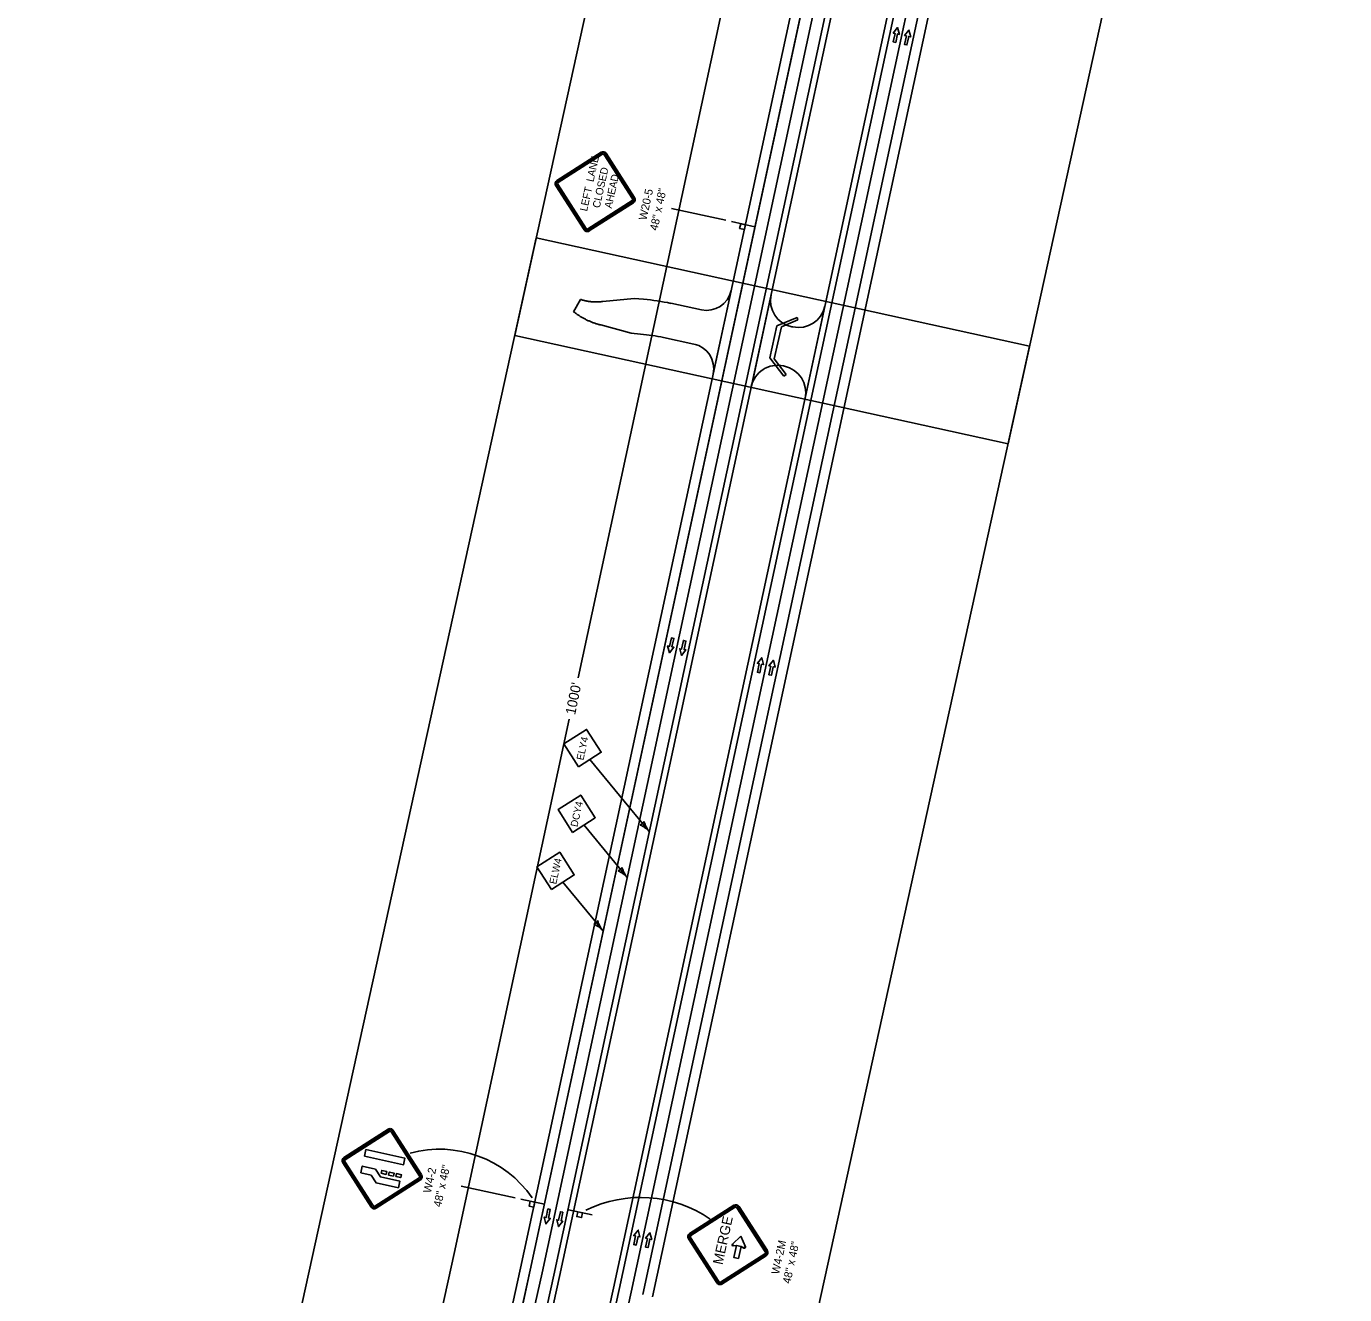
# Model space of a CAD drawing. Extents: x 14104283 to 14121738, y 8635219 to 8671666.
# Drawn here: x 14108108 to 14109426, y 8643186 to 8644454 of the extents above; entities that cross this region are included whole.
import ezdxf

# ---------------------------------------------------------------- set-up
doc = ezdxf.new("R2010")
doc.units = 0
for name, color, linetype in [('Cell', 7, 'Continuous'), ('Default', 7, 'Continuous'), ('dsnNonPlotable', 7, 'Continuous'), ('dsnPaintExistingBrokenLaneLineWhite', 7, 'Continuous'), ('dsnPaintExistingEdgeLineLeftYellow', 7, 'Continuous'), ('dsnPaintExistingEdgeLineRightWhite', 7, 'Continuous'), ('dsnStdLabel', 7, 'Continuous'), ('dsnStgShadingPrevPav', 7, 'Continuous')]:
    doc.layers.add(name, color=color, linetype=linetype)

msp = doc.modelspace()

# ---------------------------------------------------------------- linework, layer by layer
at = {"layer": 'Cell'}
for p, q in [((14108682.3, 8644328.2), (14108638.1, 8644299.9)), ((14108682.8, 8644327.4), (14108683.7, 8644326.1)), ((14108685.4, 8644325.7), (14108686.7, 8644326.6)), ((14108715.8, 8644282.8), (14108687.5, 8644327.1)), ((14108639.5, 8644297.8), (14108638.6, 8644299.1)), ((14108637, 8644294.7), (14108665.3, 8644250.5)), ((14108637.8, 8644295.2), (14108639.1, 8644296.1)), ((14108670.4, 8644249.4), (14108714.7, 8644277.7)), ((14108713.3, 8644279.8), (14108714.2, 8644278.4)), ((14108715, 8644282.3), (14108713.7, 8644281.5)), ((14108812.7, 8644258.8), (14108836.2, 8644253.7)), ((14108667.4, 8644251.8), (14108666.1, 8644251)), ((14108669.9, 8644250.2), (14108669.1, 8644251.5)), ((14108425.2, 8643322.8), (14108469.5, 8643351.1)), ((14108469.5, 8643351.1), (14108425.2, 8643322.8)), ((14108425.7, 8643322), (14108470, 8643350.3)), ((14108470.8, 8643349), (14108426.6, 8643320.7)), ((14108500.8, 8643304.4), (14108472.5, 8643348.6)), ((14108473.9, 8643349.5), (14108502.1, 8643305.2)), ((14108474.6, 8643350), (14108502.9, 8643305.8)), ((14108502.9, 8643305.8), (14108474.6, 8643350)), ((14108452.4, 8643273.4), (14108424.1, 8643317.6)), ((14108424.1, 8643317.6), (14108452.4, 8643273.4)), ((14108424.1, 8643317.6), (14108424.1, 8643317.6)), ((14108453.2, 8643273.9), (14108424.9, 8643318.1)), ((14108426.2, 8643319), (14108426.2, 8643319)), ((14108426.2, 8643319), (14108454.5, 8643274.8)), ((14108456.2, 8643274.4), (14108500.5, 8643302.7)), ((14108501.3, 8643301.4), (14108457.1, 8643273.1)), ((14108501.8, 8643300.6), (14108457.6, 8643272.3)), ((14108457.6, 8643272.3), (14108501.8, 8643300.6)), ((14108602.2, 8643281.2), (14108625.7, 8643276.1)), ((14108649.9, 8643270.7), (14108673.3, 8643265.6)), ((14108815.1, 8643275.2), (14108770.9, 8643246.9)), ((14108815.6, 8643274.4), (14108816.5, 8643273.1)), ((14108818.2, 8643272.7), (14108819.5, 8643273.5)), ((14108848.6, 8643229.8), (14108820.3, 8643274)), ((14108770.5, 8643242.2), (14108771.9, 8643243)), ((14108772.2, 8643244.8), (14108771.4, 8643246.1)), ((14108769.7, 8643241.7), (14108798, 8643197.5)), ((14108814.4, 8643235.6), (14108813.7, 8643236.4)), ((14108814.5, 8643234.6), (14108814.4, 8643235.6)), ((14108825.7, 8643233.2), (14108825.2, 8643232.3)), ((14108826.7, 8643233.5), (14108825.7, 8643233.2)), ((14108847.8, 8643229.3), (14108846.5, 8643228.5)), ((14108803.2, 8643196.3), (14108847.4, 8643224.6)), ((14108846.1, 8643226.7), (14108846.9, 8643225.4)), ((14108800.1, 8643198.8), (14108798.8, 8643198)), ((14108802.7, 8643197.1), (14108801.9, 8643198.4))]:
    msp.add_line(p, q, dxfattribs=at)
for points in [[(14108976.9, 8644437.9), (14108974.4, 8644438.4), (14108976.3, 8644446.9), (14108974.5, 8644447.3), (14108978.8, 8644452.8), (14108980.6, 8644446), (14108978.7, 8644446.4)], [(14108988.2, 8644435.4), (14108985.7, 8644435.9), (14108987.6, 8644444.5), (14108985.8, 8644444.9), (14108990.1, 8644450.3), (14108991.9, 8644443.5), (14108990, 8644443.9)], [(14108682.8, 8644327.4), (14108638.6, 8644299.1), (14108639.5, 8644297.8), (14108683.7, 8644326.1), (14108682.8, 8644327.4)], [(14108715, 8644282.3), (14108686.7, 8644326.6), (14108685.4, 8644325.7), (14108713.7, 8644281.5), (14108715, 8644282.3)], [(14108637.8, 8644295.2), (14108666.1, 8644251), (14108667.4, 8644251.8), (14108639.1, 8644296.1), (14108637.8, 8644295.2)], [(14108669.9, 8644250.2), (14108714.2, 8644278.4), (14108713.3, 8644279.8), (14108669.1, 8644251.5), (14108669.9, 8644250.2)], [(14108826.7, 8644255.7), (14108822, 8644256.7), (14108820.9, 8644251.9), (14108825.7, 8644250.9)], [(14108752.6, 8643842.5), (14108755.1, 8643842), (14108753.2, 8643833.5), (14108755.1, 8643833.1), (14108750.7, 8643827.6), (14108748.9, 8643834.4), (14108750.8, 8643834)], [(14108764.7, 8643839.9), (14108767.2, 8643839.3), (14108765.3, 8643830.8), (14108767.1, 8643830.4), (14108762.7, 8643825), (14108761, 8643831.7), (14108762.8, 8643831.3)], [(14108841.1, 8643807.7), (14108838.6, 8643808.2), (14108840.5, 8643816.8), (14108838.7, 8643817.2), (14108843, 8643822.6), (14108844.8, 8643815.8), (14108842.9, 8643816.2)], [(14108852.6, 8643805.1), (14108850.2, 8643805.7), (14108852, 8643814.2), (14108850.2, 8643814.6), (14108854.6, 8643820.1), (14108856.3, 8643813.3), (14108854.5, 8643813.7)], [(14108445.8, 8643324.2), (14108484.9, 8643315.6), (14108486.3, 8643322.2), (14108447.2, 8643330.8)], [(14108452.5, 8643305.4), (14108457.5, 8643297.5), (14108479.8, 8643292.6), (14108481.3, 8643299.2), (14108461.7, 8643303.5), (14108456.7, 8643311.4), (14108443.6, 8643314.3), (14108442.2, 8643307.7)], [(14108462.5, 8643307.1), (14108463.1, 8643310), (14108468, 8643308.9), (14108467.4, 8643306)], [(14108469.8, 8643305.4), (14108470.5, 8643308.4), (14108475.4, 8643307.3), (14108474.7, 8643304.4)], [(14108477.2, 8643303.8), (14108477.8, 8643306.8), (14108482.7, 8643305.7), (14108482, 8643302.8)], [(14108616.2, 8643278.1), (14108611.4, 8643279.1), (14108610.4, 8643274.3), (14108615.2, 8643273.3)], [(14108629.2, 8643271.5), (14108631.6, 8643270.9), (14108629.8, 8643262.4), (14108631.6, 8643262), (14108627.2, 8643256.5), (14108625.5, 8643263.3), (14108627.3, 8643262.9)], [(14108815.6, 8643274.4), (14108771.4, 8643246.1), (14108772.2, 8643244.8), (14108816.5, 8643273.1), (14108815.6, 8643274.4)], [(14108847.8, 8643229.3), (14108819.5, 8643273.5), (14108818.2, 8643272.7), (14108846.5, 8643228.5), (14108847.8, 8643229.3)], [(14108641.7, 8643268.7), (14108644.1, 8643268.2), (14108642.3, 8643259.6), (14108644.1, 8643259.2), (14108639.7, 8643253.8), (14108638, 8643260.6), (14108639.8, 8643260.2)], [(14108663.9, 8643267.6), (14108659.1, 8643268.6), (14108658.1, 8643263.8), (14108662.9, 8643262.8)], [(14108717.5, 8643235.4), (14108715.1, 8643235.9), (14108716.9, 8643244.5), (14108715.1, 8643244.9), (14108719.5, 8643250.3), (14108721.2, 8643243.5), (14108719.4, 8643243.9)], [(14108729.3, 8643232.8), (14108726.8, 8643233.3), (14108728.7, 8643241.9), (14108726.9, 8643242.3), (14108731.2, 8643247.7), (14108733, 8643240.9), (14108731.1, 8643241.3)], [(14108770.5, 8643242.2), (14108798.8, 8643198), (14108800.1, 8643198.8), (14108771.9, 8643243), (14108770.5, 8643242.2)], [(14108822.2, 8643244.3), (14108813.7, 8643236.4), (14108814.4, 8643235.6), (14108814.5, 8643234.6), (14108817.6, 8643235), (14108822.5, 8643233.9), (14108825.2, 8643232.3), (14108825.7, 8643233.2), (14108826.7, 8643233.5), (14108822.2, 8643244.3)], [(14108819.9, 8643222), (14108815, 8643223), (14108817.6, 8643235), (14108822.5, 8643233.9), (14108819.9, 8643222)], [(14108802.7, 8643197.1), (14108846.9, 8643225.4), (14108846.1, 8643226.7), (14108801.9, 8643198.4), (14108802.7, 8643197.1)]]:
    msp.add_lwpolyline(points, close=True, dxfattribs=at)
for points in [[(14108978.7, 8644446.4), (14108980.6, 8644446), (14108978.8, 8644452.8), (14108974.5, 8644447.3), (14108976.3, 8644446.9), (14108974.4, 8644438.4), (14108976.9, 8644437.9), (14108978.7, 8644446.4)], [(14108990, 8644443.9), (14108991.9, 8644443.5), (14108990.1, 8644450.3), (14108985.8, 8644444.9), (14108987.6, 8644444.5), (14108985.7, 8644435.9), (14108988.2, 8644435.4), (14108990, 8644443.9)], [(14108826.7, 8644255.7), (14108822, 8644256.7), (14108820.9, 8644251.9), (14108825.7, 8644250.9), (14108826.7, 8644255.7)], [(14108750.8, 8643834), (14108748.9, 8643834.4), (14108750.7, 8643827.6), (14108755.1, 8643833.1), (14108753.2, 8643833.5), (14108755.1, 8643842), (14108752.6, 8643842.5), (14108750.8, 8643834)], [(14108762.8, 8643831.3), (14108761, 8643831.7), (14108762.7, 8643825), (14108767.1, 8643830.4), (14108765.3, 8643830.8), (14108767.2, 8643839.3), (14108764.7, 8643839.9), (14108762.8, 8643831.3)], [(14108842.9, 8643816.2), (14108844.8, 8643815.8), (14108843, 8643822.6), (14108838.7, 8643817.2), (14108840.5, 8643816.8), (14108838.6, 8643808.2), (14108841.1, 8643807.7), (14108842.9, 8643816.2)], [(14108854.5, 8643813.7), (14108856.3, 8643813.3), (14108854.6, 8643820.1), (14108850.2, 8643814.6), (14108852, 8643814.2), (14108850.2, 8643805.7), (14108852.6, 8643805.1), (14108854.5, 8643813.7)], [(14108470, 8643350.3), (14108425.7, 8643322)], [(14108470.8, 8643349), (14108426.6, 8643320.7)], [(14108500.8, 8643304.4), (14108472.5, 8643348.6)], [(14108502.1, 8643305.2), (14108473.9, 8643349.5)], [(14108424.9, 8643318.1), (14108453.2, 8643273.9)], [(14108426.2, 8643319), (14108454.5, 8643274.8)], [(14108456.2, 8643274.4), (14108500.5, 8643302.7)], [(14108457.1, 8643273.1), (14108501.3, 8643301.4)], [(14108616.2, 8643278.1), (14108611.4, 8643279.1), (14108610.4, 8643274.3), (14108615.2, 8643273.3), (14108616.2, 8643278.1)], [(14108627.3, 8643262.9), (14108625.5, 8643263.3), (14108627.2, 8643256.5), (14108631.6, 8643262), (14108629.8, 8643262.4), (14108631.6, 8643270.9), (14108629.2, 8643271.5), (14108627.3, 8643262.9)], [(14108639.8, 8643260.2), (14108638, 8643260.6), (14108639.7, 8643253.8), (14108644.1, 8643259.2), (14108642.3, 8643259.6), (14108644.1, 8643268.2), (14108641.7, 8643268.7), (14108639.8, 8643260.2)], [(14108663.9, 8643267.6), (14108659.1, 8643268.6), (14108658.1, 8643263.8), (14108662.9, 8643262.8), (14108663.9, 8643267.6)], [(14108719.4, 8643243.9), (14108721.2, 8643243.5), (14108719.5, 8643250.3), (14108715.1, 8643244.9), (14108716.9, 8643244.5), (14108715.1, 8643235.9), (14108717.5, 8643235.4), (14108719.4, 8643243.9)], [(14108731.1, 8643241.3), (14108733, 8643240.9), (14108731.2, 8643247.7), (14108726.9, 8643242.3), (14108728.7, 8643241.9), (14108726.8, 8643233.3), (14108729.3, 8643232.8), (14108731.1, 8643241.3)]]:
    msp.add_lwpolyline(points, dxfattribs=at)
for centre, radius, start, end in [((14108684.4, 8644325), 3.75, 32.608, 122.6076), ((14108684.4, 8644325), 2.81, 32.608, 122.6076), ((14108684.4, 8644325), 1.25, 32.608, 122.6076), ((14108640.1, 8644296.7), 3.75, 122.6078, 212.6076), ((14108640.1, 8644296.7), 2.81, 122.6078, 212.6076), ((14108640.1, 8644296.7), 1.25, 122.6078, 212.6076), ((14108712.7, 8644280.8), 1.25, 302.6078, 32.608), ((14108712.7, 8644280.8), 2.81, 302.6078, 32.608), ((14108712.7, 8644280.8), 3.75, 302.6078, 32.608), ((14108668.4, 8644252.5), 3.75, 212.6076, 302.6078), ((14108668.4, 8644252.5), 2.81, 212.6076, 302.6078), ((14108668.4, 8644252.5), 1.25, 212.6076, 302.6078), ((14108471.5, 8643348), 3.75, 32.6079, 122.6081), ((14108471.5, 8643348), 3.75, 32.6079, 122.6081), ((14108471.5, 8643348), 2.81, 32.6079, 122.6081), ((14108471.5, 8643348), 2.81, 32.6079, 122.6081), ((14108471.5, 8643348), 1.25, 32.6079, 122.6081), ((14108471.5, 8643348), 1.25, 32.6079, 122.6081), ((14108427.3, 8643319.7), 3.75, 122.6081, 212.6078), ((14108427.3, 8643319.7), 3.75, 122.6081, 212.6078), ((14108427.3, 8643319.7), 2.81, 122.6081, 212.6078), ((14108427.3, 8643319.7), 2.81, 122.6081, 212.6078), ((14108427.3, 8643319.7), 1.25, 122.6081, 212.6078), ((14108427.3, 8643319.7), 1.25, 122.6081, 212.6078), ((14108499.8, 8643303.7), 1.25, 302.6077, 32.6079), ((14108499.8, 8643303.7), 1.25, 302.6077, 32.6079), ((14108499.8, 8643303.7), 2.81, 302.6077, 32.6079), ((14108499.8, 8643303.7), 2.81, 302.6077, 32.6079), ((14108499.8, 8643303.7), 3.75, 302.6077, 32.6079), ((14108499.8, 8643303.7), 3.75, 302.6077, 32.6079), ((14108455.6, 8643275.4), 3.75, 212.608, 302.6077), ((14108455.6, 8643275.4), 3.75, 212.608, 302.6077), ((14108455.6, 8643275.4), 2.81, 212.608, 302.6077), ((14108455.6, 8643275.4), 2.81, 212.608, 302.6077), ((14108455.6, 8643275.4), 1.25, 212.608, 302.6077), ((14108455.6, 8643275.4), 1.25, 212.608, 302.6077), ((14108817.1, 8643272), 3.75, 32.608, 122.6076), ((14108817.1, 8643272), 2.81, 32.608, 122.6076), ((14108817.1, 8643272), 1.25, 32.608, 122.6076), ((14108772.9, 8643243.7), 3.75, 122.6078, 212.6076), ((14108772.9, 8643243.7), 2.81, 122.6078, 212.6076), ((14108772.9, 8643243.7), 1.25, 122.6078, 212.6076), ((14108814.4, 8643235.6), 1.02, 135.2955, 276.1893), ((14108825.7, 8643233.2), 1.02, 239.0261, 19.9204), ((14108845.4, 8643227.8), 2.81, 302.6078, 32.608), ((14108845.4, 8643227.8), 3.75, 302.6078, 32.608), ((14108845.4, 8643227.8), 1.25, 302.6078, 32.608), ((14108801.2, 8643199.5), 3.75, 212.6076, 302.6078), ((14108801.2, 8643199.5), 2.81, 212.6076, 302.6078), ((14108801.2, 8643199.5), 1.25, 212.6076, 302.6078)]:
    msp.add_arc(centre, radius, start, end, dxfattribs=at)
at = {"layer": 'Default'}
for p, q in [((14108700.5, 8643190.8), (14109065.3, 8644884.7)), ((14109088.7, 8644879.7), (14108724, 8643185.8)), ((14108294.7, 8641343.2), (14108700.5, 8643190.9))]:
    msp.add_line(p, q, dxfattribs=at)
for points in [[(14108976.3, 8644903.9), (14108611.6, 8643210.2), (14108202.1, 8641346.1)], [(14108434.9, 8642294.1), (14108635.1, 8643205.1), (14108999.8, 8644898.8)]]:
    msp.add_lwpolyline(points, dxfattribs=at)
at = {"layer": 'dsnNonPlotable'}
for points in [[(14108596.1, 8644144.9), (14108932.5, 8645675.8), (14109425.7, 8645567.5), (14109089.3, 8644036.5)], [(14108281.2, 8642711.6), (14108617.6, 8644242.5), (14109110.8, 8644134.2), (14108774.4, 8642603.2)]]:
    msp.add_lwpolyline(points, close=True, dxfattribs=at)
at = {"layer": 'dsnPaintExistingBrokenLaneLineWhite'}
for p, q in [((14108623.3, 8643207.7), (14108988, 8644901.3)), ((14108213.8, 8641343.5), (14108623.3, 8643207.7))]:
    msp.add_line(p, q, dxfattribs=at)
msp.add_lwpolyline([(14108306.4, 8641340.7), (14108389, 8641717), (14108712.3, 8643188.3), (14108894.6, 8644035.3), (14109077, 8644882.2)], dxfattribs=at)
at = {"layer": 'dsnPaintExistingEdgeLineLeftYellow'}
for p, q in [((14108700.5, 8643190.8), (14109065.3, 8644884.7)), ((14108199.6, 8640910.3), (14108700.5, 8643190.8))]:
    msp.add_line(p, q, dxfattribs=at)
msp.add_lwpolyline([(14108999.8, 8644898.8), (14108635.1, 8643205.1), (14108434.9, 8642294.1)], dxfattribs=at)
at = {"layer": 'dsnPaintExistingEdgeLineRightWhite'}
msp.add_line((14108724, 8643185.8), (14109088.7, 8644879.7), dxfattribs=at)
msp.add_lwpolyline([(14108976.3, 8644903.9), (14108611.6, 8643210.2), (14108202.1, 8641346.1)], dxfattribs=at)
at = {"layer": 'dsnStdLabel'}
for p, q in [((14108861.2, 8644740.1), (14108659.4, 8643802.5)), ((14108752.9, 8644272), (14108807, 8644260.1)), ((14108851, 8644122.6), (14108858.2, 8644154.6)), ((14108855.5, 8644121.6), (14108862.7, 8644153.5)), ((14108858.2, 8644154.6), (14108878.4, 8644163)), ((14108862.7, 8644153.5), (14108879.2, 8644160.4)), ((14108878.4, 8644163), (14108879.2, 8644160.4)), ((14108851, 8644122.6), (14108865, 8644104.1)), ((14108855.5, 8644121.6), (14108867.3, 8644106)), ((14108865, 8644104.1), (14108867.3, 8644106)), ((14108671.1, 8643720.9), (14108730.5, 8643649)), ((14108665.3, 8643655.3), (14108708.4, 8643603)), ((14108644.1, 8643598.2), (14108684.1, 8643549.8)), ((14108542.4, 8643294.4), (14108596.5, 8643282.5))]:
    msp.add_line(p, q, dxfattribs=at)
msp.add_lwpolyline([(14108650.5, 8643761.2), (14108535.4, 8643226.8), (14108446.7, 8642823.1)], dxfattribs=at)
for points in [[(14108659.7, 8643713.6), (14108682.5, 8643728.2), (14108667.9, 8643750.9), (14108645.2, 8643736.4)], [(14108653.9, 8643648), (14108676.6, 8643662.6), (14108662.1, 8643685.3), (14108639.3, 8643670.8)], [(14108632.8, 8643590.9), (14108655.5, 8643605.5), (14108641, 8643628.2), (14108618.2, 8643613.7)]]:
    msp.add_lwpolyline(points, close=True, dxfattribs=at)
for centre, radius, start, end in [((14108718, 8643663.6), 8.86, 292.8385, 328.307), ((14108713, 8643634), 22.9, 40.5727, 68.6439), ((14108747.9, 8643663.9), 22.9, 192.5015, 220.5728), ((14108695.9, 8643617.6), 8.86, 292.8385, 328.307), ((14108725.9, 8643617.9), 22.9, 192.5015, 220.5728), ((14108691, 8643588.1), 22.9, 40.5727, 68.6439), ((14108671.6, 8643564.4), 8.86, 292.8385, 328.307), ((14108701.5, 8643564.7), 22.9, 192.5015, 220.5728), ((14108666.7, 8643534.8), 22.9, 40.5727, 68.6439), ((14108520.9, 8643218.9), 112.3, 34.5988, 105.2065), ((14108721.8, 8643160.3), 122.7, 55.4671, 116.4111)]:
    msp.add_arc(centre, radius, start, end, dxfattribs=at)
at = {"layer": 'dsnStgShadingPrevPav'}
for p, q in [((14108601.8, 8643212.3), (14108966.5, 8644906)), ((14108976.3, 8644903.9), (14108611.6, 8643210.2)), ((14109059.4, 8644886), (14108694.7, 8643192.1)), ((14108733.8, 8643183.6), (14109098.5, 8644877.6)), ((14108654.9, 8644168.7), (14108661.9, 8644180.9)), ((14108684, 8644178.9), (14108715.4, 8644182)), ((14108715.4, 8644182), (14108724.9, 8644181.2)), ((14108812.3, 8644189.7), (14108794.4, 8644106.6)), ((14108832.6, 8644093.8), (14108852.3, 8644185.7)), ((14108752.2, 8644177.1), (14108782.6, 8644170.5)), ((14108906.1, 8644174.1), (14108886.3, 8644082.2)), ((14108712.4, 8644147.1), (14108682, 8644155.4)), ((14108873.1, 8644153.6), (14108874, 8644153.4)), ((14108721.9, 8644146.3), (14108712.4, 8644147.1)), ((14108775.2, 8644136.3), (14108744.9, 8644142.9)), ((14108865.6, 8644114.3), (14108864.6, 8644114.5)), ((14108107.8, 8640963.3), (14108601.8, 8643212.3)), ((14108611.6, 8643210.2), (14108117.6, 8640961.2)), ((14108694.7, 8643192.1), (14108383, 8641773.2))]:
    msp.add_line(p, q, dxfattribs=at)
for points in [[(14108202.1, 8641346.1), (14108611.6, 8643210.2), (14108976.3, 8644903.9)], [(14108999.8, 8644898.8), (14108817.4, 8644052), (14108635.1, 8643205.1), (14108387.9, 8642080.1), (14108140.8, 8640955.1)], [(14108146.7, 8640953.8), (14108640.9, 8643203.9), (14109005.6, 8644897.6)], [(14108999.8, 8644898.8), (14108635.1, 8643205.1), (14108225.5, 8641340.9)]]:
    msp.add_lwpolyline(points, dxfattribs=at)
for centre, radius, start, end in [((14108706.4, 8643964.4), 217.5, 77.8488, 85.1347), ((14108787.9, 8644195), 25, 257.8488, 347.8488), ((14108878.7, 8644180), 27, 167.8488, 257.8488), ((14108879.7, 8644179.8), 27, 257.8488, 347.8488), ((14108706.4, 8643964.4), 182.5, 77.8488, 85.1347), ((14108770, 8644111.9), 25, 347.8488, 77.8488), ((14108858.9, 8644088.1), 27, 77.8488, 167.8488), ((14108859.9, 8644087.9), 27, 347.8488, 77.8488)]:
    msp.add_arc(centre, radius, start, end, dxfattribs=at)
for points in [[(14108661.9, 8644180.9), (14108662.2, 8644180.8), (14108663, 8644180.5), (14108664.1, 8644180.2), (14108665.2, 8644179.9), (14108666.3, 8644179.7), (14108667.5, 8644179.4), (14108668.6, 8644179.2), (14108669.7, 8644179), (14108670.8, 8644178.9), (14108671.9, 8644178.7), (14108673.1, 8644178.6), (14108674.2, 8644178.5), (14108675.3, 8644178.5), (14108676.4, 8644178.4), (14108677.5, 8644178.4), (14108678.6, 8644178.4), (14108679.7, 8644178.5), (14108680.8, 8644178.6), (14108681.8, 8644178.6), (14108682.9, 8644178.8), (14108683.6, 8644178.9), (14108684, 8644178.9)], [(14108682, 8644155.4), (14108681.5, 8644155.6), (14108680.5, 8644155.8), (14108679, 8644156.2), (14108677.5, 8644156.7), (14108676, 8644157.2), (14108674.5, 8644157.7), (14108673.1, 8644158.2), (14108671.7, 8644158.8), (14108670.3, 8644159.4), (14108668.9, 8644160), (14108667.5, 8644160.7), (14108666.1, 8644161.4), (14108664.8, 8644162.1), (14108663.5, 8644162.8), (14108662.2, 8644163.6), (14108660.9, 8644164.4), (14108659.7, 8644165.2), (14108658.5, 8644166), (14108657.3, 8644166.9), (14108656.1, 8644167.8), (14108655.3, 8644168.4), (14108654.9, 8644168.7)]]:
    msp.add_open_spline(points, degree=3, dxfattribs=at)

# ---------------------------------------------------------------- texts
at = {"layer": 'Cell'}
for s, height, p in [('LEFT  LANE', 7.5, (14108668.3, 8644268.6)), ('CLOSED', 7.5, (14108681, 8644271.9)), ('AHEAD', 7.5, (14108692.9, 8644271.5)), ('W20-5', 8, (14108727.7, 8644259.7)), ('48" x 48"', 8, (14108738.7, 8644249.3)), ('W4-2', 8, (14108512.2, 8643286.8)), ('48" x 48"', 8, (14108522.4, 8643272.9)), ('MERGE', 10, (14108803.7, 8643215.1)), ('W4-2M', 8, (14108860.2, 8643205.5)), ('48" x 48"', 8, (14108871.5, 8643196.2))]:
    msp.add_text(s, height=height, rotation=77.6078, dxfattribs=at).set_placement(p)
at = {"layer": 'dsnStdLabel'}
for s, height, rotation, p in [("1000'", 10, 78.5531, (14108656.4, 8643765)), ('ELY4', 7.2, 77.6078, (14108664.7, 8643719.7)), ('DCY4', 7.2, 77.6078, (14108658.7, 8643653)), ('ELW4', 7.2, 77.6078, (14108637.5, 8643595.7))]:
    msp.add_text(s, height=height, rotation=rotation, dxfattribs=at).set_placement(p)

doc.saveas('drawing.dxf')
